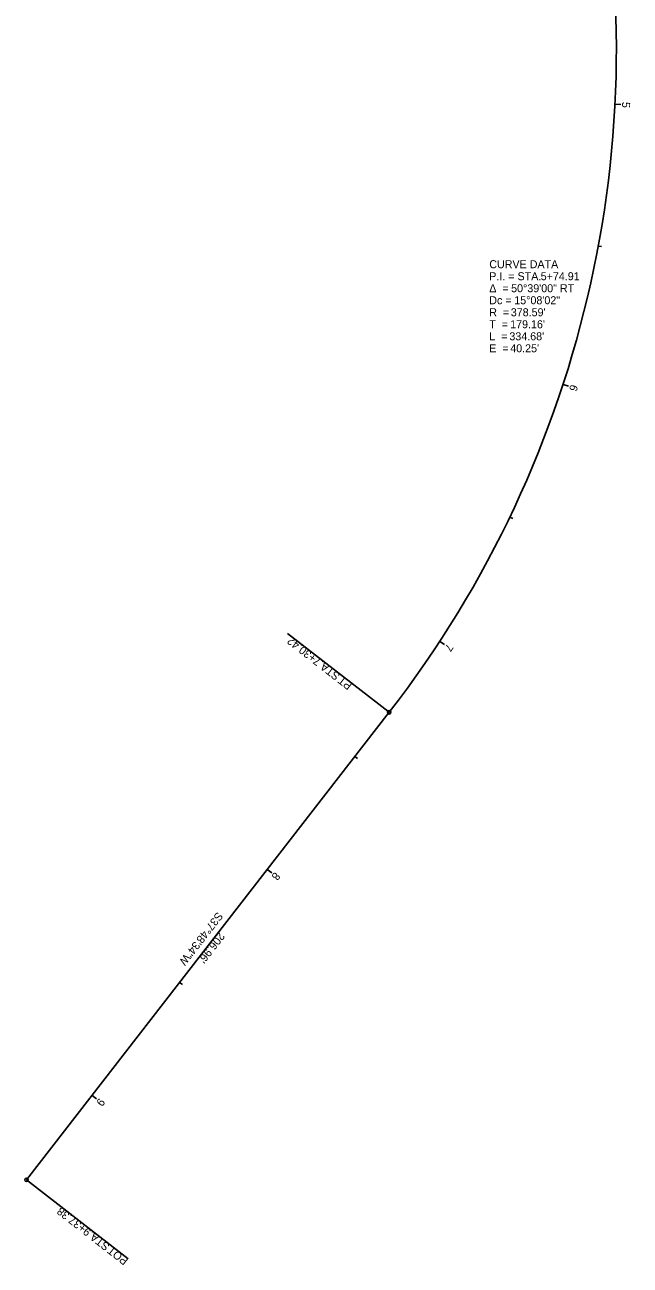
# Model space of a CAD drawing. Extents: x 2376685 to 2376908, y 700340 to 701208.
# Drawn here: x 2376696 to 2376907.8, y 700340.5 to 700774.3 of the extents above; entities that cross this region are included whole.
import ezdxf

# ---------------------------------------------------------------- set-up
doc = ezdxf.new("R2010")
doc.units = 0
for name, color, linetype in [('Default', 7, 'Continuous'), ('GE_X_Alignment', 7, 'Continuous'), ('GE_X_Alignment_100_Bearings', 7, 'Continuous'), ('GE_X_Alignment_100_Cardinal_Points', 7, 'Continuous'), ('GE_X_Alignment_100_Curve_Data', 7, 'Continuous'), ('GE_X_Alignment_100_Distances', 7, 'Continuous'), ('GE_X_Alignment_100_Stations', 7, 'Continuous')]:
    doc.layers.add(name, color=color, linetype=linetype)

msp = doc.modelspace()

# ---------------------------------------------------------------- linework, layer by layer
at = {"layer": 'Default'}
msp.add_line((2376823.49, 700533.83), (2376696.61, 700370.32), dxfattribs=at)
msp.add_arc((2376524.38, 700765.92), 378.59, 322.1906, 12.8405, dxfattribs=at)
at = {"layer": 'GE_X_Alignment'}
msp.add_line((2376823.49, 700533.83), (2376696.61, 700370.32), dxfattribs=at)
msp.add_arc((2376524.38, 700765.92), 378.59, 322.1906, 12.8405, dxfattribs=at)
at = {"layer": 'GE_X_Alignment_100_Cardinal_Points'}
for p, q in [((2376823.49, 700533.83), (2376787.93, 700561.42)), ((2376696.61, 700370.32), (2376732.17, 700342.74))]:
    msp.add_line(p, q, dxfattribs=at)
for centre in [(2376823.49, 700533.83), (2376696.61, 700370.32)]:
    msp.add_circle(centre, 0.6, dxfattribs=at)
at = {"layer": 'GE_X_Alignment_100_Stations'}
for p, q in [((2376902.47, 700746.52), (2376904.47, 700746.42)), ((2376896.63, 700696.9), (2376897.81, 700696.68)), ((2376884.3, 700648.48), (2376886.2, 700647.86)), ((2376865.7, 700602.11), (2376866.78, 700601.59)), ((2376841.15, 700558.59), (2376842.83, 700557.5)), ((2376811.49, 700518.36), (2376812.43, 700517.63)), ((2376780.83, 700478.86), (2376782.41, 700477.64)), ((2376750.18, 700439.36), (2376751.13, 700438.62)), ((2376719.53, 700399.86), (2376721.11, 700398.63))]:
    msp.add_line(p, q, dxfattribs=at)

# ---------------------------------------------------------------- texts
at = {"layer": 'GE_X_Alignment_100_Bearings'}
msp.add_text('S37°48\'34"W', height=2.8, rotation=232.1906, dxfattribs=at).set_placement((2376763.38, 700464.2))
at = {"layer": 'GE_X_Alignment_100_Cardinal_Points'}
for s, p in [('7+30.42', (2376799.96, 700552.04)), (' STA. ', (2376807.32, 700546.33)), ('PT', (2376810.76, 700543.66)), ('9+37.38', (2376719.42, 700352.58)), (' STA. ', (2376726.79, 700346.86)), ('POT', (2376732.42, 700342.49))]:
    msp.add_text(s, height=2.8, rotation=142.1906, dxfattribs=at).set_placement(p)
at = {"layer": 'GE_X_Alignment_100_Curve_Data'}
for s, p in [('CURVE DATA', (2376858.5, 700689.14)), ('P.I. = STA. ', (2376858.5, 700684.94)), ('5+74.91', (2376876.49, 700684.94)), ('Δ  = ', (2376858.5, 700680.74)), ('50°39\'00" RT', (2376866.14, 700680.74)), ('Dc = ', (2376858.5, 700676.54)), ('15°08\'02"', (2376867.24, 700676.54)), ('R  = ', (2376858.5, 700672.34)), ("378.59'", (2376866.03, 700672.34)), ('T  = ', (2376858.5, 700668.14)), ("179.16'", (2376865.81, 700668.14)), ('L  = ', (2376858.5, 700663.94)), ("334.68'", (2376865.53, 700663.94)), ('E  = ', (2376858.5, 700659.74)), ("40.25'", (2376865.84, 700659.74))]:
    msp.add_text(s, height=2.8, dxfattribs=at).set_placement(p)
at = {"layer": 'GE_X_Alignment_100_Distances'}
msp.add_text("206.96'", height=2.8, rotation=232.1906, dxfattribs=at).set_placement((2376764.03, 700457.14))
at = {"layer": 'GE_X_Alignment_100_Stations'}
for s, rotation, p in [('5', 267.0627, (2376905.02, 700747.36)), ('6', 251.9287, (2376886.99, 700648.68)), ('7', 236.7947, (2376843.8, 700558.06)), ('8', 232.1906, (2376783.43, 700478.13)), ('9', 232.1906, (2376722.11, 700399.11))]:
    msp.add_text(s, height=2.8, rotation=rotation, dxfattribs=at).set_placement(p)

doc.saveas('drawing.dxf')
